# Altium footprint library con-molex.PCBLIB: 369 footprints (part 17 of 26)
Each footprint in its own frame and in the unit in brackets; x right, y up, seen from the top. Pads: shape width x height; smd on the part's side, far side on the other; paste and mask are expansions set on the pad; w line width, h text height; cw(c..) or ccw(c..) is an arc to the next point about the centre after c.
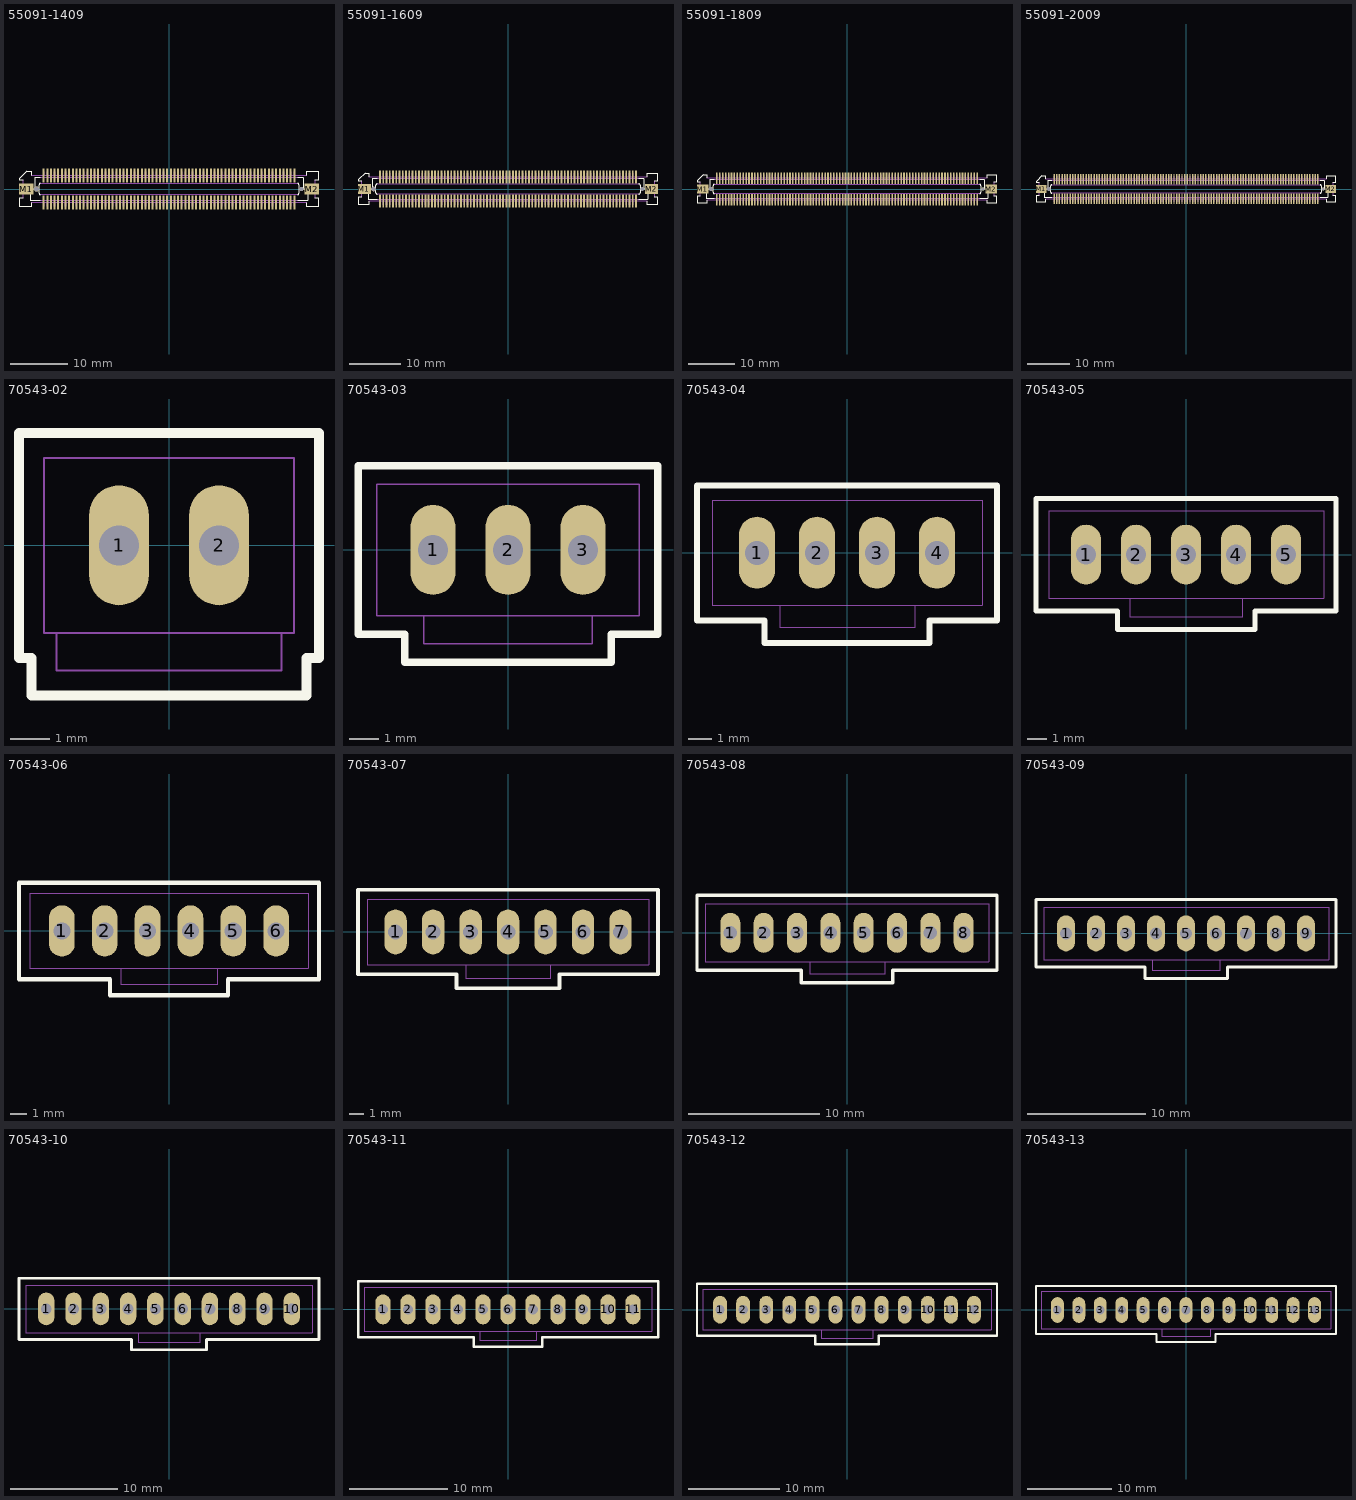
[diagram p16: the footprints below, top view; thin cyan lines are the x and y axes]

## 55091-1409 [mm]
pads (144):
  round 0.9 hole 0.9: 1(-23.16,0)
  rect 0.35x2.5 smd: 1(-21.907,2.35) 2(-21.907,-2.35) 3(-21.273,2.35) 4(-21.273,-2.35) 5(-20.637,2.35) 6(-20.637,-2.35) 7(-20.002,2.35) 8(-20.002,-2.35) 9(-19.367,2.35) 10(-19.367,-2.35) 11(-18.732,2.35) 12(-18.732,-2.35) 13(-18.098,2.35) 14(-18.098,-2.35) 15(-17.462,2.35) 16(-17.462,-2.35) 17(-16.828,2.35) 18(-16.828,-2.35) 19(-16.192,2.35) 20(-16.192,-2.35) 21(-15.557,2.35) 22(-15.557,-2.35) 23(-14.922,2.35) 24(-14.922,-2.35) 25(-14.287,2.35) 26(-14.287,-2.35) 27(-13.652,2.35) 28(-13.652,-2.35) 29(-13.018,2.35) 30(-13.018,-2.35) 31(-12.383,2.35) 32(-12.383,-2.35) 33(-11.747,2.35) 34(-11.747,-2.35) 35(-11.112,2.35) 36(-11.112,-2.35) 37(-10.477,2.35) 38(-10.477,-2.35) 39(-9.842,2.35) 40(-9.842,-2.35) 41(-9.207,2.35) 42(-9.207,-2.35) 43(-8.572,2.35) 44(-8.572,-2.35) 45(-7.938,2.35) 46(-7.938,-2.35) 47(-7.302,2.35) 48(-7.302,-2.35) 49(-6.667,2.35) 50(-6.667,-2.35) 51(-6.032,2.35) 52(-6.032,-2.35) 53(-5.397,2.35) 54(-5.397,-2.35) 55(-4.763,2.35) 56(-4.763,-2.35) 57(-4.127,2.35) 58(-4.127,-2.35) 59(-3.492,2.35) 60(-3.492,-2.35) 61(-2.857,2.35) 62(-2.857,-2.35) 63(-2.222,2.35) 64(-2.222,-2.35) 65(-1.587,2.35) 66(-1.587,-2.35) 67(-0.953,2.35) 68(-0.953,-2.35) 69(-0.318,2.35) 70(-0.318,-2.35) 71(0.318,2.35) 72(0.318,-2.35) 73(0.953,2.35) 74(0.953,-2.35) 75(1.587,2.35) 76(1.587,-2.35) 77(2.222,2.35) 78(2.222,-2.35) 79(2.857,2.35) 80(2.857,-2.35) 81(3.492,2.35) 82(3.492,-2.35) 83(4.127,2.35) 84(4.127,-2.35) 85(4.763,2.35) 86(4.763,-2.35) 87(5.397,2.35) 88(5.397,-2.35) 89(6.032,2.35) 90(6.032,-2.35) 91(6.667,2.35) 92(6.667,-2.35) 93(7.302,2.35) 94(7.302,-2.35) 95(7.938,2.35) 96(7.938,-2.35) 97(8.572,2.35) 98(8.572,-2.35) 99(9.207,2.35) 100(9.207,-2.35) 101(9.842,2.35) 102(9.842,-2.35) 103(10.477,2.35) 104(10.477,-2.35) 105(11.112,2.35) 106(11.112,-2.35) 107(11.747,2.35) 108(11.747,-2.35) 109(12.383,2.35) 110(12.383,-2.35) 111(13.018,2.35) 112(13.018,-2.35) 113(13.652,2.35) 114(13.652,-2.35) 115(14.287,2.35) 116(14.287,-2.35) 117(14.922,2.35) 118(14.922,-2.35) 119(15.557,2.35) 120(15.557,-2.35) 121(16.192,2.35) 122(16.192,-2.35) 123(16.828,2.35) 124(16.828,-2.35) 125(17.462,2.35) 126(17.462,-2.35) 127(18.098,2.35) 128(18.098,-2.35) 129(18.732,2.35) 130(18.732,-2.35) 131(19.367,2.35) 132(19.367,-2.35) 133(20.002,2.35) 134(20.002,-2.35) 135(20.637,2.35) 136(20.637,-2.35) 137(21.273,2.35) 138(21.273,-2.35) 139(21.907,2.35) 140(21.907,-2.35)
  round 0.7 hole 0.7: 1(23.16,0)
  rect 2.5x2 smd: M1(-24.975,0) M2(24.975,0)
Top Overlay:
  lines w0.203: -25.475,-1.5 -26.075,-1.5 -26.075,-3.1 -24.075,-3.1 -24.075,-2.4 ; -25.475,1.5 -26.075,1.5 -26.075,1.875 -24.85,3.1 -24.075,3.1 -24.075,2.4 ; -22.475,-2 -24.225,-2 -24.225,0 -23.475,0 -23.475,2 -22.475,2 ; -22.475,-1 cw(c-22.475,-0.75) -22.725,-0.75 -22.725,0.75 cw(c-22.475,0.75) -22.475,1 ; 22.475,-2 24.225,-2 24.225,0 23.475,0 23.475,2 22.475,2 ; 22.475,-1 ccw(c22.475,-0.75) 22.725,-0.75 22.725,0.75 ccw(c22.475,0.75) 22.475,1 ; 24.075,-2.4 24.075,-3.1 26.075,-3.1 26.075,-1.5 25.475,-1.5 ; 24.075,2.4 24.075,3.1 26.075,3.1 26.075,1.5 25.475,1.5
Top Solder:
  rectangle: -22.107,1.075 -21.708,3.625
  region: -21.708,-1.075 -22.107,-1.075 -22.107,-3.625 -21.708,-3.625
  rectangle: -21.472,1.075 -21.073,3.625
  region: -21.073,-1.075 -21.472,-1.075 -21.472,-3.625 -21.073,-3.625
  rectangle: -20.837,1.075 -20.438,3.625
  region: -20.438,-1.075 -20.837,-1.075 -20.837,-3.625 -20.438,-3.625
  rectangle: -20.202,1.075 -19.803,3.625
  region: -19.803,-1.075 -20.202,-1.075 -20.202,-3.625 -19.803,-3.625
  rectangle: -19.567,1.075 -19.168,3.625
  region: -19.168,-1.075 -19.567,-1.075 -19.567,-3.625 -19.168,-3.625
  rectangle: -18.932,1.075 -18.533,3.625
  region: -18.533,-1.075 -18.932,-1.075 -18.932,-3.625 -18.533,-3.625
  rectangle: -18.297,1.075 -17.898,3.625
  region: -17.898,-1.075 -18.297,-1.075 -18.297,-3.625 -17.898,-3.625
  rectangle: -17.662,1.075 -17.263,3.625
  region: -17.263,-1.075 -17.662,-1.075 -17.662,-3.625 -17.263,-3.625
  rectangle: -17.027,1.075 -16.628,3.625
  region: -16.628,-1.075 -17.027,-1.075 -17.027,-3.625 -16.628,-3.625
  rectangle: -16.392,1.075 -15.993,3.625
  region: -15.993,-1.075 -16.392,-1.075 -16.392,-3.625 -15.993,-3.625
  rectangle: -15.757,1.075 -15.358,3.625
  region: -15.358,-1.075 -15.757,-1.075 -15.757,-3.625 -15.358,-3.625
  rectangle: -15.122,1.075 -14.723,3.625
  region: -14.723,-1.075 -15.122,-1.075 -15.122,-3.625 -14.723,-3.625
  rectangle: -14.487,1.075 -14.088,3.625
  region: -14.088,-1.075 -14.487,-1.075 -14.487,-3.625 -14.088,-3.625
  rectangle: -13.852,1.075 -13.453,3.625
  region: -13.453,-1.075 -13.852,-1.075 -13.852,-3.625 -13.453,-3.625
  rectangle: -13.217,1.075 -12.818,3.625
  region: -12.818,-1.075 -13.217,-1.075 -13.217,-3.625 -12.818,-3.625
  rectangle: -12.582,1.075 -12.183,3.625
  region: -12.183,-1.075 -12.582,-1.075 -12.582,-3.625 -12.183,-3.625
  rectangle: -11.947,1.075 -11.548,3.625
  region: -11.548,-1.075 -11.947,-1.075 -11.947,-3.625 -11.548,-3.625
  rectangle: -11.312,1.075 -10.913,3.625
  region: -10.913,-1.075 -11.312,-1.075 -11.312,-3.625 -10.913,-3.625
  rectangle: -10.677,1.075 -10.278,3.625
  region: -10.278,-1.075 -10.677,-1.075 -10.677,-3.625 -10.278,-3.625
  rectangle: -10.042,1.075 -9.643,3.625
  region: -9.643,-1.075 -10.042,-1.075 -10.042,-3.625 -9.643,-3.625
  rectangle: -9.407,1.075 -9.008,3.625
  region: -9.008,-1.075 -9.407,-1.075 -9.407,-3.625 -9.008,-3.625
  rectangle: -8.772,1.075 -8.373,3.625
  region: -8.373,-1.075 -8.772,-1.075 -8.772,-3.625 -8.373,-3.625
  rectangle: -8.137,1.075 -7.738,3.625
  region: -7.738,-1.075 -8.137,-1.075 -8.137,-3.625 -7.738,-3.625
  rectangle: -7.502,1.075 -7.103,3.625
  region: -7.103,-1.075 -7.502,-1.075 -7.502,-3.625 -7.103,-3.625
  rectangle: -6.867,1.075 -6.468,3.625
  region: -6.468,-1.075 -6.867,-1.075 -6.867,-3.625 -6.468,-3.625
  rectangle: -6.232,1.075 -5.833,3.625
  region: -5.833,-1.075 -6.232,-1.075 -6.232,-3.625 -5.833,-3.625
  rectangle: -5.597,1.075 -5.198,3.625
  region: -5.198,-1.075 -5.597,-1.075 -5.597,-3.625 -5.198,-3.625
  rectangle: -4.962,1.075 -4.563,3.625
  region: -4.563,-1.075 -4.962,-1.075 -4.962,-3.625 -4.563,-3.625
  rectangle: -4.327,1.075 -3.928,3.625
  region: -3.928,-1.075 -4.327,-1.075 -4.327,-3.625 -3.928,-3.625
  rectangle: -3.692,1.075 -3.293,3.625
  region: -3.293,-1.075 -3.692,-1.075 -3.692,-3.625 -3.293,-3.625
  rectangle: -3.057,1.075 -2.658,3.625
  region: -2.658,-1.075 -3.057,-1.075 -3.057,-3.625 -2.658,-3.625
  rectangle: -2.422,1.075 -2.023,3.625
  region: -2.023,-1.075 -2.422,-1.075 -2.422,-3.625 -2.023,-3.625
  rectangle: -1.787,1.075 -1.388,3.625
  region: -1.388,-1.075 -1.787,-1.075 -1.787,-3.625 -1.388,-3.625
  rectangle: -1.152,1.075 -0.753,3.625
  region: -0.753,-1.075 -1.152,-1.075 -1.152,-3.625 -0.753,-3.625
  rectangle: -0.517,1.075 -0.118,3.625
  region: -0.118,-1.075 -0.517,-1.075 -0.517,-3.625 -0.118,-3.625
  rectangle: 0.118,1.075 0.517,3.625
  region: 0.517,-1.075 0.118,-1.075 0.118,-3.625 0.517,-3.625
  rectangle: 0.753,1.075 1.152,3.625
  region: 1.152,-1.075 0.753,-1.075 0.753,-3.625 1.152,-3.625
  rectangle: 1.388,1.075 1.787,3.625
  region: 1.787,-1.075 1.388,-1.075 1.388,-3.625 1.787,-3.625
  rectangle: 2.023,1.075 2.422,3.625
  region: 2.422,-1.075 2.023,-1.075 2.023,-3.625 2.422,-3.625
  rectangle: 2.658,1.075 3.057,3.625
  region: 3.057,-1.075 2.658,-1.075 2.658,-3.625 3.057,-3.625
  rectangle: 3.293,1.075 3.692,3.625
  region: 3.692,-1.075 3.293,-1.075 3.293,-3.625 3.692,-3.625
  rectangle: 3.928,1.075 4.327,3.625
  region: 4.327,-1.075 3.928,-1.075 3.928,-3.625 4.327,-3.625
  rectangle: 4.563,1.075 4.962,3.625
  region: 4.962,-1.075 4.563,-1.075 4.563,-3.625 4.962,-3.625
  rectangle: 5.198,1.075 5.597,3.625
  region: 5.597,-1.075 5.198,-1.075 5.198,-3.625 5.597,-3.625
  rectangle: 5.833,1.075 6.232,3.625
  region: 6.232,-1.075 5.833,-1.075 5.833,-3.625 6.232,-3.625
  rectangle: 6.468,1.075 6.867,3.625
  region: 6.867,-1.075 6.468,-1.075 6.468,-3.625 6.867,-3.625
  rectangle: 7.103,1.075 7.502,3.625
  region: 7.502,-1.075 7.103,-1.075 7.103,-3.625 7.502,-3.625
  rectangle: 7.738,1.075 8.137,3.625
  region: 8.137,-1.075 7.738,-1.075 7.738,-3.625 8.137,-3.625
  rectangle: 8.373,1.075 8.772,3.625
  region: 8.772,-1.075 8.373,-1.075 8.373,-3.625 8.772,-3.625
  rectangle: 9.008,1.075 9.407,3.625
  region: 9.407,-1.075 9.008,-1.075 9.008,-3.625 9.407,-3.625
  rectangle: 9.643,1.075 10.042,3.625
  region: 10.042,-1.075 9.643,-1.075 9.643,-3.625 10.042,-3.625
  rectangle: 10.278,1.075 10.677,3.625
  region: 10.677,-1.075 10.278,-1.075 10.278,-3.625 10.677,-3.625
  rectangle: 10.913,1.075 11.312,3.625
  region: 11.312,-1.075 10.913,-1.075 10.913,-3.625 11.312,-3.625
  rectangle: 11.548,1.075 11.947,3.625
  region: 11.947,-1.075 11.548,-1.075 11.548,-3.625 11.947,-3.625
  rectangle: 12.183,1.075 12.582,3.625
  region: 12.582,-1.075 12.183,-1.075 12.183,-3.625 12.582,-3.625
  rectangle: 12.818,1.075 13.217,3.625
  region: 13.217,-1.075 12.818,-1.075 12.818,-3.625 13.217,-3.625
  rectangle: 13.453,1.075 13.852,3.625
  region: 13.852,-1.075 13.453,-1.075 13.453,-3.625 13.852,-3.625
  rectangle: 14.088,1.075 14.487,3.625
  region: 14.487,-1.075 14.088,-1.075 14.088,-3.625 14.487,-3.625
  rectangle: 14.723,1.075 15.122,3.625
  region: 15.122,-1.075 14.723,-1.075 14.723,-3.625 15.122,-3.625
  rectangle: 15.358,1.075 15.757,3.625
  region: 15.757,-1.075 15.358,-1.075 15.358,-3.625 15.757,-3.625
  rectangle: 15.993,1.075 16.392,3.625
  region: 16.392,-1.075 15.993,-1.075 15.993,-3.625 16.392,-3.625
  rectangle: 16.628,1.075 17.027,3.625
  region: 17.027,-1.075 16.628,-1.075 16.628,-3.625 17.027,-3.625
  rectangle: 17.263,1.075 17.662,3.625
  region: 17.662,-1.075 17.263,-1.075 17.263,-3.625 17.662,-3.625
  rectangle: 17.898,1.075 18.297,3.625
  region: 18.297,-1.075 17.898,-1.075 17.898,-3.625 18.297,-3.625
  rectangle: 18.533,1.075 18.932,3.625
  region: 18.932,-1.075 18.533,-1.075 18.533,-3.625 18.932,-3.625
  rectangle: 19.168,1.075 19.567,3.625
  region: 19.567,-1.075 19.168,-1.075 19.168,-3.625 19.567,-3.625
  rectangle: 19.803,1.075 20.202,3.625
  region: 20.202,-1.075 19.803,-1.075 19.803,-3.625 20.202,-3.625
  rectangle: 20.438,1.075 20.837,3.625
  region: 20.837,-1.075 20.438,-1.075 20.438,-3.625 20.837,-3.625
  rectangle: 21.073,1.075 21.472,3.625
  region: 21.472,-1.075 21.073,-1.075 21.073,-3.625 21.472,-3.625
  rectangle: 21.708,1.075 22.107,3.625
  region: 22.107,-1.075 21.708,-1.075 21.708,-3.625 22.107,-3.625
Mechanical 16:
  rectangle: -22.058,-3.1 -21.757,-2.375
  region: -21.757,3.1 -22.058,3.1 -22.058,2.375 -21.757,2.375
  rectangle: -21.423,-3.1 -21.122,-2.375
  region: -21.122,3.1 -21.423,3.1 -21.423,2.375 -21.122,2.375
  rectangle: -20.788,-3.1 -20.487,-2.375
  region: -20.487,3.1 -20.788,3.1 -20.788,2.375 -20.487,2.375
  rectangle: -20.153,-3.1 -19.852,-2.375
  region: -19.852,3.1 -20.153,3.1 -20.153,2.375 -19.852,2.375
  rectangle: -19.518,-3.1 -19.217,-2.375
  region: -19.217,3.1 -19.518,3.1 -19.518,2.375 -19.217,2.375
  rectangle: -18.883,-3.1 -18.582,-2.375
  region: -18.582,3.1 -18.883,3.1 -18.883,2.375 -18.582,2.375
  rectangle: -18.248,-3.1 -17.947,-2.375
  region: -17.947,3.1 -18.248,3.1 -18.248,2.375 -17.947,2.375
  rectangle: -17.613,-3.1 -17.312,-2.375
  region: -17.312,3.1 -17.613,3.1 -17.613,2.375 -17.312,2.375
  rectangle: -16.978,-3.1 -16.677,-2.375
  region: -16.677,3.1 -16.978,3.1 -16.978,2.375 -16.677,2.375
  rectangle: -16.343,-3.1 -16.042,-2.375
  region: -16.042,3.1 -16.343,3.1 -16.343,2.375 -16.042,2.375
  rectangle: -15.708,-3.1 -15.407,-2.375
  region: -15.407,3.1 -15.708,3.1 -15.708,2.375 -15.407,2.375
  rectangle: -15.073,-3.1 -14.772,-2.375
  region: -14.772,3.1 -15.073,3.1 -15.073,2.375 -14.772,2.375
  rectangle: -14.438,-3.1 -14.137,-2.375
  region: -14.137,3.1 -14.438,3.1 -14.438,2.375 -14.137,2.375
  rectangle: -13.803,-3.1 -13.502,-2.375
  region: -13.502,3.1 -13.803,3.1 -13.803,2.375 -13.502,2.375
  rectangle: -13.168,-3.1 -12.867,-2.375
  region: -12.867,3.1 -13.168,3.1 -13.168,2.375 -12.867,2.375
  rectangle: -12.533,-3.1 -12.232,-2.375
  region: -12.232,3.1 -12.533,3.1 -12.533,2.375 -12.232,2.375
  rectangle: -11.898,-3.1 -11.597,-2.375
  region: -11.597,3.1 -11.898,3.1 -11.898,2.375 -11.597,2.375
  rectangle: -11.263,-3.1 -10.962,-2.375
  region: -10.962,3.1 -11.263,3.1 -11.263,2.375 -10.962,2.375
  rectangle: -10.628,-3.1 -10.327,-2.375
  region: -10.327,3.1 -10.628,3.1 -10.628,2.375 -10.327,2.375
  rectangle: -9.993,-3.1 -9.692,-2.375
  region: -9.692,3.1 -9.993,3.1 -9.993,2.375 -9.692,2.375
  rectangle: -9.358,-3.1 -9.057,-2.375
  region: -9.057,3.1 -9.358,3.1 -9.358,2.375 -9.057,2.375
  rectangle: -8.723,-3.1 -8.422,-2.375
  region: -8.422,3.1 -8.723,3.1 -8.723,2.375 -8.422,2.375
  rectangle: -8.088,-3.1 -7.787,-2.375
  region: -7.787,3.1 -8.088,3.1 -8.088,2.375 -7.787,2.375
  rectangle: -7.453,-3.1 -7.152,-2.375
  region: -7.152,3.1 -7.453,3.1 -7.453,2.375 -7.152,2.375
  rectangle: -6.818,-3.1 -6.517,-2.375
  region: -6.517,3.1 -6.818,3.1 -6.818,2.375 -6.517,2.375
  rectangle: -6.183,-3.1 -5.882,-2.375
  region: -5.882,3.1 -6.183,3.1 -6.183,2.375 -5.882,2.375
  rectangle: -5.548,-3.1 -5.247,-2.375
  region: -5.247,3.1 -5.548,3.1 -5.548,2.375 -5.247,2.375
  rectangle: -4.913,-3.1 -4.612,-2.375
  region: -4.612,3.1 -4.913,3.1 -4.913,2.375 -4.612,2.375
  rectangle: -4.278,-3.1 -3.977,-2.375
  region: -3.977,3.1 -4.278,3.1 -4.278,2.375 -3.977,2.375
  rectangle: -3.643,-3.1 -3.342,-2.375
  region: -3.342,3.1 -3.643,3.1 -3.643,2.375 -3.342,2.375
  rectangle: -3.008,-3.1 -2.707,-2.375
  region: -2.707,3.1 -3.008,3.1 -3.008,2.375 -2.707,2.375
  rectangle: -2.373,-3.1 -2.072,-2.375
  region: -2.072,3.1 -2.373,3.1 -2.373,2.375 -2.072,2.375
  rectangle: -1.738,-3.1 -1.437,-2.375
  region: -1.437,3.1 -1.738,3.1 -1.738,2.375 -1.437,2.375
  rectangle: -1.103,-3.1 -0.802,-2.375
  region: -0.802,3.1 -1.103,3.1 -1.103,2.375 -0.802,2.375
  rectangle: -0.468,-3.1 -0.167,-2.375
  region: -0.167,3.1 -0.468,3.1 -0.468,2.375 -0.167,2.375
  rectangle: 0.167,-3.1 0.468,-2.375
  region: 0.468,3.1 0.167,3.1 0.167,2.375 0.468,2.375
  rectangle: 0.802,-3.1 1.103,-2.375
  region: 1.103,3.1 0.802,3.1 0.802,2.375 1.103,2.375
  rectangle: 1.437,-3.1 1.738,-2.375
  region: 1.738,3.1 1.437,3.1 1.437,2.375 1.738,2.375
  rectangle: 2.072,-3.1 2.373,-2.375
  region: 2.373,3.1 2.072,3.1 2.072,2.375 2.373,2.375
  rectangle: 2.707,-3.1 3.008,-2.375
  region: 3.008,3.1 2.707,3.1 2.707,2.375 3.008,2.375
  rectangle: 3.342,-3.1 3.643,-2.375
  region: 3.643,3.1 3.342,3.1 3.342,2.375 3.643,2.375
  rectangle: 3.977,-3.1 4.278,-2.375
  region: 4.278,3.1 3.977,3.1 3.977,2.375 4.278,2.375
  rectangle: 4.612,-3.1 4.913,-2.375
  region: 4.913,3.1 4.612,3.1 4.612,2.375 4.913,2.375
  rectangle: 5.247,-3.1 5.548,-2.375
  region: 5.548,3.1 5.247,3.1 5.247,2.375 5.548,2.375
  rectangle: 5.882,-3.1 6.183,-2.375
  region: 6.183,3.1 5.882,3.1 5.882,2.375 6.183,2.375
  rectangle: 6.517,-3.1 6.818,-2.375
  region: 6.818,3.1 6.517,3.1 6.517,2.375 6.818,2.375
  rectangle: 7.152,-3.1 7.453,-2.375
  region: 7.453,3.1 7.152,3.1 7.152,2.375 7.453,2.375
  rectangle: 7.787,-3.1 8.088,-2.375
  region: 8.088,3.1 7.787,3.1 7.787,2.375 8.088,2.375
  rectangle: 8.422,-3.1 8.723,-2.375
  region: 8.723,3.1 8.422,3.1 8.422,2.375 8.723,2.375
  rectangle: 9.057,-3.1 9.358,-2.375
  region: 9.358,3.1 9.057,3.1 9.057,2.375 9.358,2.375
  rectangle: 9.692,-3.1 9.993,-2.375
  region: 9.993,3.1 9.692,3.1 9.692,2.375 9.993,2.375
  rectangle: 10.327,-3.1 10.628,-2.375
  region: 10.628,3.1 10.327,3.1 10.327,2.375 10.628,2.375
  rectangle: 10.962,-3.1 11.263,-2.375
  region: 11.263,3.1 10.962,3.1 10.962,2.375 11.263,2.375
  rectangle: 11.597,-3.1 11.898,-2.375
  region: 11.898,3.1 11.597,3.1 11.597,2.375 11.898,2.375
  rectangle: 12.232,-3.1 12.533,-2.375
  region: 12.533,3.1 12.232,3.1 12.232,2.375 12.533,2.375
  rectangle: 12.867,-3.1 13.168,-2.375
  region: 13.168,3.1 12.867,3.1 12.867,2.375 13.168,2.375
  rectangle: 13.502,-3.1 13.803,-2.375
  region: 13.803,3.1 13.502,3.1 13.502,2.375 13.803,2.375
  rectangle: 14.137,-3.1 14.438,-2.375
  region: 14.438,3.1 14.137,3.1 14.137,2.375 14.438,2.375
  rectangle: 14.772,-3.1 15.073,-2.375
  region: 15.073,3.1 14.772,3.1 14.772,2.375 15.073,2.375
  rectangle: 15.407,-3.1 15.708,-2.375
  region: 15.708,3.1 15.407,3.1 15.407,2.375 15.708,2.375
  rectangle: 16.042,-3.1 16.343,-2.375
  region: 16.343,3.1 16.042,3.1 16.042,2.375 16.343,2.375
  rectangle: 16.677,-3.1 16.978,-2.375
  region: 16.978,3.1 16.677,3.1 16.677,2.375 16.978,2.375
  rectangle: 17.312,-3.1 17.613,-2.375
  region: 17.613,3.1 17.312,3.1 17.312,2.375 17.613,2.375
  rectangle: 17.947,-3.1 18.248,-2.375
  region: 18.248,3.1 17.947,3.1 17.947,2.375 18.248,2.375
  rectangle: 18.582,-3.1 18.883,-2.375
  region: 18.883,3.1 18.582,3.1 18.582,2.375 18.883,2.375
  rectangle: 19.217,-3.1 19.518,-2.375
  region: 19.518,3.1 19.217,3.1 19.217,2.375 19.518,2.375
  rectangle: 19.852,-3.1 20.153,-2.375
  region: 20.153,3.1 19.852,3.1 19.852,2.375 20.153,2.375
  rectangle: 20.487,-3.1 20.788,-2.375
  region: 20.788,3.1 20.487,3.1 20.487,2.375 20.788,2.375
  rectangle: 21.122,-3.1 21.423,-2.375
  region: 21.423,3.1 21.122,3.1 21.122,2.375 21.423,2.375
  rectangle: 21.757,-3.1 22.058,-2.375
  region: 22.058,3.1 21.757,3.1 21.757,2.375 22.058,2.375
  lines w0.203: -25.475,-1.5 -25.475,1.5 ; -24.075,-2.4 24.075,-2.4 ; -24.075,2.4 24.075,2.4 ; -22.475,-2 22.475,-2 ; -22.475,-1 22.475,-1 ; -22.475,1 22.475,1 ; -22.475,2 22.475,2 ; 25.475,-1.5 25.475,1.5

## 55091-1609 [mm]
pads (164):
  round 0.9 hole 0.9: 1(-26.335,0)
  rect 0.35x2.5 smd: 1(-25.082,2.35) 2(-25.082,-2.35) 3(-24.447,2.35) 4(-24.447,-2.35) 5(-23.812,2.35) 6(-23.812,-2.35) 7(-23.177,2.35) 8(-23.177,-2.35) 9(-22.543,2.35) 10(-22.543,-2.35) 11(-21.907,2.35) 12(-21.907,-2.35) 13(-21.273,2.35) 14(-21.273,-2.35) 15(-20.637,2.35) 16(-20.637,-2.35) 17(-20.002,2.35) 18(-20.002,-2.35) 19(-19.367,2.35) 20(-19.367,-2.35) 21(-18.732,2.35) 22(-18.732,-2.35) 23(-18.098,2.35) 24(-18.098,-2.35) 25(-17.462,2.35) 26(-17.462,-2.35) 27(-16.828,2.35) 28(-16.828,-2.35) 29(-16.192,2.35) 30(-16.192,-2.35) 31(-15.557,2.35) 32(-15.557,-2.35) 33(-14.922,2.35) 34(-14.922,-2.35) 35(-14.287,2.35) 36(-14.287,-2.35) 37(-13.652,2.35) 38(-13.652,-2.35) 39(-13.018,2.35) 40(-13.018,-2.35) 41(-12.383,2.35) 42(-12.383,-2.35) 43(-11.747,2.35) 44(-11.747,-2.35) 45(-11.112,2.35) 46(-11.112,-2.35) 47(-10.477,2.35) 48(-10.477,-2.35) 49(-9.842,2.35) 50(-9.842,-2.35) 51(-9.207,2.35) 52(-9.207,-2.35) 53(-8.572,2.35) 54(-8.572,-2.35) 55(-7.938,2.35) 56(-7.938,-2.35) 57(-7.302,2.35) 58(-7.302,-2.35) 59(-6.667,2.35) 60(-6.667,-2.35) 61(-6.032,2.35) 62(-6.032,-2.35) 63(-5.397,2.35) 64(-5.397,-2.35) 65(-4.763,2.35) 66(-4.763,-2.35) 67(-4.127,2.35) 68(-4.127,-2.35) 69(-3.492,2.35) 70(-3.492,-2.35) 71(-2.857,2.35) 72(-2.857,-2.35) 73(-2.222,2.35) 74(-2.222,-2.35) 75(-1.587,2.35) 76(-1.587,-2.35) 77(-0.953,2.35) 78(-0.953,-2.35) 79(-0.318,2.35) 80(-0.318,-2.35) 81(0.318,2.35) 82(0.318,-2.35) 83(0.953,2.35) 84(0.953,-2.35) 85(1.587,2.35) 86(1.587,-2.35) 87(2.222,2.35) 88(2.222,-2.35) 89(2.857,2.35) 90(2.857,-2.35) 91(3.492,2.35) 92(3.492,-2.35) 93(4.127,2.35) 94(4.127,-2.35) 95(4.763,2.35) 96(4.763,-2.35) 97(5.397,2.35) 98(5.397,-2.35) 99(6.032,2.35) 100(6.032,-2.35) 101(6.667,2.35) 102(6.667,-2.35) 103(7.302,2.35) 104(7.302,-2.35) 105(7.938,2.35) 106(7.938,-2.35) 107(8.572,2.35) 108(8.572,-2.35) 109(9.207,2.35) 110(9.207,-2.35) 111(9.842,2.35) 112(9.842,-2.35) 113(10.477,2.35) 114(10.477,-2.35) 115(11.112,2.35) 116(11.112,-2.35) 117(11.747,2.35) 118(11.747,-2.35) 119(12.383,2.35) 120(12.383,-2.35) 121(13.018,2.35) 122(13.018,-2.35) 123(13.652,2.35) 124(13.652,-2.35) 125(14.287,2.35) 126(14.287,-2.35) 127(14.922,2.35) 128(14.922,-2.35) 129(15.557,2.35) 130(15.557,-2.35) 131(16.192,2.35) 132(16.192,-2.35) 133(16.828,2.35) 134(16.828,-2.35) 135(17.462,2.35) 136(17.462,-2.35) 137(18.098,2.35) 138(18.098,-2.35) 139(18.732,2.35) 140(18.732,-2.35) 141(19.367,2.35) 142(19.367,-2.35) 143(20.002,2.35) 144(20.002,-2.35) 145(20.637,2.35) 146(20.637,-2.35) 147(21.273,2.35) 148(21.273,-2.35) 149(21.907,2.35) 150(21.907,-2.35) 151(22.543,2.35) 152(22.543,-2.35) 153(23.177,2.35) 154(23.177,-2.35) 155(23.812,2.35) 156(23.812,-2.35) 157(24.447,2.35) 158(24.447,-2.35) 159(25.082,2.35) 160(25.082,-2.35)
  round 0.7 hole 0.7: 1(26.335,0)
  rect 2.5x2 smd: M1(-28.15,0) M2(28.15,0)
Top Overlay:
  lines w0.203: -28.65,-1.5 -29.25,-1.5 -29.25,-3.1 -27.25,-3.1 -27.25,-2.4 ; -28.65,1.5 -29.25,1.5 -29.25,1.875 -28.025,3.1 -27.25,3.1 -27.25,2.4 ; -25.65,-2 -27.4,-2 -27.4,0 -26.65,0 -26.65,2 -25.65,2 ; -25.65,-1 cw(c-25.65,-0.75) -25.9,-0.75 -25.9,0.75 cw(c-25.65,0.75) -25.65,1 ; 25.65,-2 27.4,-2 27.4,0 26.65,0 26.65,2 25.65,2 ; 25.65,-1 ccw(c25.65,-0.75) 25.9,-0.75 25.9,0.75 ccw(c25.65,0.75) 25.65,1 ; 27.25,-2.4 27.25,-3.1 29.25,-3.1 29.25,-1.5 28.65,-1.5 ; 27.25,2.4 27.25,3.1 29.25,3.1 29.25,1.5 28.65,1.5
Top Solder:
  drawing of 160 lines, arcs and shapes, not listed
Mechanical 16:
  drawing of 168 lines, arcs and shapes, not listed

## 55091-1809 [mm]
pads (184):
  round 0.9 hole 0.9: 1(-29.51,0)
  rect 0.35x2.5 smd: 1(-28.258,2.35) 2(-28.258,-2.35) 3(-27.622,2.35) 4(-27.622,-2.35) 5(-26.987,2.35) 6(-26.987,-2.35) 7(-26.352,2.35) 8(-26.352,-2.35) 9(-25.717,2.35) 10(-25.717,-2.35) 11(-25.082,2.35) 12(-25.082,-2.35) 13(-24.447,2.35) 14(-24.447,-2.35) 15(-23.812,2.35) 16(-23.812,-2.35) 17(-23.177,2.35) 18(-23.177,-2.35) 19(-22.543,2.35) 20(-22.543,-2.35) 21(-21.907,2.35) 22(-21.907,-2.35) 23(-21.273,2.35) 24(-21.273,-2.35) 25(-20.637,2.35) 26(-20.637,-2.35) 27(-20.002,2.35) 28(-20.002,-2.35) 29(-19.367,2.35) 30(-19.367,-2.35) 31(-18.732,2.35) 32(-18.732,-2.35) 33(-18.098,2.35) 34(-18.098,-2.35) 35(-17.462,2.35) 36(-17.462,-2.35) 37(-16.828,2.35) 38(-16.828,-2.35) 39(-16.192,2.35) 40(-16.192,-2.35) 41(-15.557,2.35) 42(-15.557,-2.35) 43(-14.922,2.35) 44(-14.922,-2.35) 45(-14.287,2.35) 46(-14.287,-2.35) 47(-13.652,2.35) 48(-13.652,-2.35) 49(-13.018,2.35) 50(-13.018,-2.35) 51(-12.383,2.35) 52(-12.383,-2.35) 53(-11.747,2.35) 54(-11.747,-2.35) 55(-11.112,2.35) 56(-11.112,-2.35) 57(-10.477,2.35) 58(-10.477,-2.35) 59(-9.842,2.35) 60(-9.842,-2.35) 61(-9.207,2.35) 62(-9.207,-2.35) 63(-8.572,2.35) 64(-8.572,-2.35) 65(-7.938,2.35) 66(-7.938,-2.35) 67(-7.302,2.35) 68(-7.302,-2.35) 69(-6.667,2.35) 70(-6.667,-2.35) 71(-6.032,2.35) 72(-6.032,-2.35) 73(-5.397,2.35) 74(-5.397,-2.35) 75(-4.763,2.35) 76(-4.763,-2.35) 77(-4.127,2.35) 78(-4.127,-2.35) 79(-3.492,2.35) 80(-3.492,-2.35) 81(-2.857,2.35) 82(-2.857,-2.35) 83(-2.222,2.35) 84(-2.222,-2.35) 85(-1.587,2.35) 86(-1.587,-2.35) 87(-0.953,2.35) 88(-0.953,-2.35) 89(-0.318,2.35) 90(-0.318,-2.35) 91(0.318,2.35) 92(0.318,-2.35) 93(0.953,2.35) 94(0.953,-2.35) 95(1.587,2.35) 96(1.587,-2.35) 97(2.222,2.35) 98(2.222,-2.35) 99(2.857,2.35) 100(2.857,-2.35) 101(3.492,2.35) 102(3.492,-2.35) 103(4.127,2.35) 104(4.127,-2.35) 105(4.763,2.35) 106(4.763,-2.35) 107(5.397,2.35) 108(5.397,-2.35) 109(6.032,2.35) 110(6.032,-2.35) 111(6.667,2.35) 112(6.667,-2.35) 113(7.302,2.35) 114(7.302,-2.35) 115(7.938,2.35) 116(7.938,-2.35) 117(8.572,2.35) 118(8.572,-2.35) 119(9.207,2.35) 120(9.207,-2.35) 121(9.842,2.35) 122(9.842,-2.35) 123(10.477,2.35) 124(10.477,-2.35) 125(11.112,2.35) 126(11.112,-2.35) 127(11.747,2.35) 128(11.747,-2.35) 129(12.383,2.35) 130(12.383,-2.35) 131(13.018,2.35) 132(13.018,-2.35) 133(13.652,2.35) 134(13.652,-2.35) 135(14.287,2.35) 136(14.287,-2.35) 137(14.922,2.35) 138(14.922,-2.35) 139(15.557,2.35) 140(15.557,-2.35) 141(16.192,2.35) 142(16.192,-2.35) 143(16.828,2.35) 144(16.828,-2.35) 145(17.462,2.35) 146(17.462,-2.35) 147(18.098,2.35) 148(18.098,-2.35) 149(18.732,2.35) 150(18.732,-2.35) 151(19.367,2.35) 152(19.367,-2.35) 153(20.002,2.35) 154(20.002,-2.35) 155(20.637,2.35) 156(20.637,-2.35) 157(21.273,2.35) 158(21.273,-2.35) 159(21.907,2.35) 160(21.907,-2.35) 161(22.543,2.35) 162(22.543,-2.35) 163(23.177,2.35) 164(23.177,-2.35) 165(23.812,2.35) 166(23.812,-2.35) 167(24.447,2.35) 168(24.447,-2.35) 169(25.082,2.35) 170(25.082,-2.35) 171(25.717,2.35) 172(25.717,-2.35) 173(26.352,2.35) 174(26.352,-2.35) 175(26.987,2.35) 176(26.987,-2.35) 177(27.622,2.35) 178(27.622,-2.35) 179(28.258,2.35) 180(28.258,-2.35)
  round 0.7 hole 0.7: 1(29.51,0)
  rect 2.5x2 smd: M1(-31.325,0) M2(31.325,0)
Top Overlay:
  lines w0.203: -31.825,-1.5 -32.425,-1.5 -32.425,-3.1 -30.425,-3.1 -30.425,-2.4 ; -31.825,1.5 -32.425,1.5 -32.425,1.875 -31.2,3.1 -30.425,3.1 -30.425,2.4 ; -28.825,-2 -30.575,-2 -30.575,0 -29.825,0 -29.825,2 -28.825,2 ; -28.825,-1 cw(c-28.825,-0.75) -29.075,-0.75 -29.075,0.75 cw(c-28.825,0.75) -28.825,1 ; 28.825,-2 30.575,-2 30.575,0 29.825,0 29.825,2 28.825,2 ; 28.825,-1 ccw(c28.825,-0.75) 29.075,-0.75 29.075,0.75 ccw(c28.825,0.75) 28.825,1 ; 30.425,-2.4 30.425,-3.1 32.425,-3.1 32.425,-1.5 31.825,-1.5 ; 30.425,2.4 30.425,3.1 32.425,3.1 32.425,1.5 31.825,1.5
Top Solder:
  drawing of 180 lines, arcs and shapes, not listed
Mechanical 16:
  drawing of 188 lines, arcs and shapes, not listed

## 55091-2009 [mm]
pads (204):
  round 0.9 hole 0.9: 1(-32.685,0)
  rect 0.35x2.5 smd: 1(-31.432,2.35) 2(-31.432,-2.35) 3(-30.797,2.35) 4(-30.797,-2.35) 5(-30.162,2.35) 6(-30.162,-2.35) 7(-29.527,2.35) 8(-29.527,-2.35) 9(-28.892,2.35) 10(-28.892,-2.35) 11(-28.258,2.35) 12(-28.258,-2.35) 13(-27.622,2.35) 14(-27.622,-2.35) 15(-26.987,2.35) 16(-26.987,-2.35) 17(-26.352,2.35) 18(-26.352,-2.35) 19(-25.717,2.35) 20(-25.717,-2.35) 21(-25.082,2.35) 22(-25.082,-2.35) 23(-24.447,2.35) 24(-24.447,-2.35) 25(-23.812,2.35) 26(-23.812,-2.35) 27(-23.177,2.35) 28(-23.177,-2.35) 29(-22.543,2.35) 30(-22.543,-2.35) 31(-21.907,2.35) 32(-21.907,-2.35) 33(-21.273,2.35) 34(-21.273,-2.35) 35(-20.637,2.35) 36(-20.637,-2.35) 37(-20.002,2.35) 38(-20.002,-2.35) 39(-19.367,2.35) 40(-19.367,-2.35) 41(-18.732,2.35) 42(-18.732,-2.35) 43(-18.098,2.35) 44(-18.098,-2.35) 45(-17.462,2.35) 46(-17.462,-2.35) 47(-16.828,2.35) 48(-16.828,-2.35) 49(-16.192,2.35) 50(-16.192,-2.35) 51(-15.557,2.35) 52(-15.557,-2.35) 53(-14.922,2.35) 54(-14.922,-2.35) 55(-14.287,2.35) 56(-14.287,-2.35) 57(-13.652,2.35) 58(-13.652,-2.35) 59(-13.018,2.35) 60(-13.018,-2.35) 61(-12.383,2.35) 62(-12.383,-2.35) 63(-11.747,2.35) 64(-11.747,-2.35) 65(-11.112,2.35) 66(-11.112,-2.35) 67(-10.477,2.35) 68(-10.477,-2.35) 69(-9.842,2.35) 70(-9.842,-2.35) 71(-9.207,2.35) 72(-9.207,-2.35) 73(-8.572,2.35) 74(-8.572,-2.35) 75(-7.938,2.35) 76(-7.938,-2.35) 77(-7.302,2.35) 78(-7.302,-2.35) 79(-6.667,2.35) 80(-6.667,-2.35) 81(-6.032,2.35) 82(-6.032,-2.35) 83(-5.397,2.35) 84(-5.397,-2.35) 85(-4.763,2.35) 86(-4.763,-2.35) 87(-4.127,2.35) 88(-4.127,-2.35) 89(-3.492,2.35) 90(-3.492,-2.35) 91(-2.857,2.35) 92(-2.857,-2.35) 93(-2.222,2.35) 94(-2.222,-2.35) 95(-1.587,2.35) 96(-1.587,-2.35) 97(-0.953,2.35) 98(-0.953,-2.35) 99(-0.318,2.35) 100(-0.318,-2.35) 101(0.318,2.35) 102(0.318,-2.35) 103(0.953,2.35) 104(0.953,-2.35) 105(1.587,2.35) 106(1.587,-2.35) 107(2.222,2.35) 108(2.222,-2.35) 109(2.857,2.35) 110(2.857,-2.35) 111(3.492,2.35) 112(3.492,-2.35) 113(4.127,2.35) 114(4.127,-2.35) 115(4.763,2.35) 116(4.763,-2.35) 117(5.397,2.35) 118(5.397,-2.35) 119(6.032,2.35) 120(6.032,-2.35) 121(6.667,2.35) 122(6.667,-2.35) 123(7.302,2.35) 124(7.302,-2.35) 125(7.938,2.35) 126(7.938,-2.35) 127(8.572,2.35) 128(8.572,-2.35) 129(9.207,2.35) 130(9.207,-2.35) 131(9.842,2.35) 132(9.842,-2.35) 133(10.477,2.35) 134(10.477,-2.35) 135(11.112,2.35) 136(11.112,-2.35) 137(11.747,2.35) 138(11.747,-2.35) 139(12.383,2.35) 140(12.383,-2.35) 141(13.018,2.35) 142(13.018,-2.35) 143(13.652,2.35) 144(13.652,-2.35) 145(14.287,2.35) 146(14.287,-2.35) 147(14.922,2.35) 148(14.922,-2.35) 149(15.557,2.35) 150(15.557,-2.35) 151(16.192,2.35) 152(16.192,-2.35) 153(16.828,2.35) 154(16.828,-2.35) 155(17.462,2.35) 156(17.462,-2.35) 157(18.098,2.35) 158(18.098,-2.35) 159(18.732,2.35) 160(18.732,-2.35) 161(19.367,2.35) 162(19.367,-2.35) 163(20.002,2.35) 164(20.002,-2.35) 165(20.637,2.35) 166(20.637,-2.35) 167(21.273,2.35) 168(21.273,-2.35) 169(21.907,2.35) 170(21.907,-2.35) 171(22.543,2.35) 172(22.543,-2.35) 173(23.177,2.35) 174(23.177,-2.35) 175(23.812,2.35) 176(23.812,-2.35) 177(24.447,2.35) 178(24.447,-2.35) 179(25.082,2.35) 180(25.082,-2.35) 181(25.717,2.35) 182(25.717,-2.35) 183(26.352,2.35) 184(26.352,-2.35) 185(26.987,2.35) 186(26.987,-2.35) 187(27.622,2.35) 188(27.622,-2.35) 189(28.258,2.35) 190(28.258,-2.35) 191(28.892,2.35) 192(28.892,-2.35) 193(29.527,2.35) 194(29.527,-2.35) 195(30.162,2.35) 196(30.162,-2.35) 197(30.797,2.35) 198(30.797,-2.35) 199(31.432,2.35) 200(31.432,-2.35)
  round 0.7 hole 0.7: 1(32.685,0)
  rect 2.5x2 smd: M1(-34.5,0) M2(34.5,0)
Top Overlay:
  lines w0.203: -35.6,-1.9 -35.6,-1.5 ; -35,-1.5 -35.6,-1.5 ; -35,1.5 -35.6,1.5 -35.6,1.875 -34.375,3.1 -33.6,3.1 -33.6,2.4 ; -34.4,-3.1 -33.6,-3.1 ; -33.6,-2.4 -33.6,-3.1 ; -32,-2 -33.75,-2 -33.75,0 -33,0 -33,2 -32,2 ; -32,-1 cw(c-32,-0.75) -32.25,-0.75 -32.25,0.75 cw(c-32,0.75) -32,1 ; 32,-2 33.75,-2 33.75,0 33,0 33,2 32,2 ; 32,-1 ccw(c32,-0.75) 32.25,-0.75 32.25,0.75 ccw(c32,0.75) 32,1 ; 33.6,-2.4 33.6,-3.1 35.6,-3.1 35.6,-1.5 35,-1.5 ; 33.6,2.4 33.6,3.1 35.6,3.1 35.6,1.5 35,1.5 ; -35.6,-1.5 -35.6,-3.1 -33.6,-3.1
Top Solder:
  drawing of 200 lines, arcs and shapes, not listed
Mechanical 16:
  drawing of 208 lines, arcs and shapes, not listed

## 70543-02 [mil]
pads (2):
  oval 60x120 hole 40: 1(-50,0) 2(50,0)
Top Overlay:
  lines w10: -150,-112.5 -150,112.5 150,112.5 150,-112.5 137.5,-112.5 137.5,-150 -137.5,-150 -137.5,-112.5 -150,-112.5
Mechanical 16:
  rectangle: 40.63,-9.37 59.37,9.37
  rectangle: -59.37,-9.37 -40.63,9.37
  lines w2: -112.5,-87.5 -125,-87.5 -125,87.5 125,87.5 125,-87.5 112.5,-87.5 ; -112.5,-87.5 112.5,-87.5 ; -112.5,-87.5 -112.5,-125 112.5,-125 112.5,-87.5
  text "1" at -112.5,-62.5 h62

## 70543-03 [mil]
pads (3):
  oval 60x120 hole 40: 1(-100,0) 2(0,0) 3(100,0)
Top Overlay:
  lines w10: -200,-112.5 -200,112.5 200,112.5 200,-112.5 137.5,-112.5 137.5,-150 -137.5,-150 -137.5,-112.5 -200,-112.5
Mechanical 16:
  rectangle: -9.37,-9.37 9.37,9.37
  rectangle: -109.37,-9.37 -90.63,9.37
  rectangle: 90.63,-9.37 109.37,9.37
  lines w2: -112.5,-87.5 -175,-87.5 -175,87.5 175,87.5 175,-87.5 112.5,-87.5 ; -112.5,-87.5 112.5,-87.5 ; -112.5,-87.5 -112.5,-125 112.5,-125 112.5,-87.5
  text "1" at -162.5,-62.5 h62

## 70543-04 [mil]
pads (4):
  oval 60x120 hole 40: 1(-150,0) 2(-50,0) 3(50,0) 4(150,0)
Top Overlay:
  lines w10: -250,-112.5 -250,112.5 250,112.5 250,-112.5 137.5,-112.5 137.5,-150 -137.5,-150 -137.5,-112.5 -250,-112.5
Mechanical 16:
  rectangle: -59.37,-9.37 -40.63,9.37
  rectangle: -159.37,-9.37 -140.63,9.37
  rectangle: 140.63,-9.37 159.37,9.37
  rectangle: 40.63,-9.37 59.37,9.37
  lines w2: -112.5,-87.5 -225,-87.5 -225,87.5 225,87.5 225,-87.5 112.5,-87.5 ; -112.5,-87.5 112.5,-87.5 ; -112.5,-87.5 -112.5,-125 112.5,-125 112.5,-87.5
  text "1" at -212.5,-62.5 h62

## 70543-05 [mil]
pads (5):
  oval 60x120 hole 40: 1(-200,0) 2(-100,0) 3(0,0) 4(100,0) 5(200,0)
Top Overlay:
  lines w10: -300,-112.5 -300,112.5 300,112.5 300,-112.5 137.5,-112.5 137.5,-150 -137.5,-150 -137.5,-112.5 -300,-112.5
Mechanical 16:
  rectangle: -109.37,-9.37 -90.63,9.37
  rectangle: -209.37,-9.37 -190.63,9.37
  rectangle: 90.63,-9.37 109.37,9.37
  rectangle: -9.37,-9.37 9.37,9.37
  rectangle: 190.63,-9.37 209.37,9.37
  lines w2: -112.5,-87.5 -275,-87.5 -275,87.5 275,87.5 275,-87.5 112.5,-87.5 ; -112.5,-87.5 112.5,-87.5 ; -112.5,-87.5 -112.5,-125 112.5,-125 112.5,-87.5
  text "1" at -262.5,-62.5 h62

## 70543-06 [mil]
pads (6):
  oval 60x120 hole 40: 1(-250,0) 2(-150,0) 3(-50,0) 4(50,0) 5(150,0) 6(250,0)
Top Overlay:
  lines w10: -350,-112.5 -350,112.5 350,112.5 350,-112.5 137.5,-112.5 137.5,-150 -137.5,-150 -137.5,-112.5 -350,-112.5
Mechanical 16:
  rectangle: -159.37,-9.37 -140.63,9.37
  rectangle: -259.37,-9.37 -240.63,9.37
  rectangle: 40.63,-9.37 59.37,9.37
  rectangle: -59.37,-9.37 -40.63,9.37
  rectangle: 240.63,-9.37 259.37,9.37
  rectangle: 140.63,-9.37 159.37,9.37
  lines w2: -112.5,-87.5 -325,-87.5 -325,87.5 325,87.5 325,-87.5 112.5,-87.5 ; -112.5,-87.5 112.5,-87.5 ; -112.5,-87.5 -112.5,-125 112.5,-125 112.5,-87.5
  text "1" at -312.5,-62.5 h62

## 70543-07 [mil]
pads (7):
  oval 60x120 hole 40: 1(-300,0) 2(-200,0) 3(-100,0) 4(0,0) 5(100,0) 6(200,0) 7(300,0)
Top Overlay:
  lines w10: -400,-112.5 -400,112.5 400,112.5 400,-112.5 137.5,-112.5 137.5,-150 -137.5,-150 -137.5,-112.5 -400,-112.5
Mechanical 16:
  rectangle: -209.37,-9.37 -190.63,9.37
  rectangle: -309.37,-9.37 -290.63,9.37
  rectangle: -9.37,-9.37 9.37,9.37
  rectangle: -109.37,-9.37 -90.63,9.37
  rectangle: 190.63,-9.37 209.37,9.37
  rectangle: 90.63,-9.37 109.37,9.37
  rectangle: 290.63,-9.37 309.37,9.37
  lines w2: -112.5,-87.5 -375,-87.5 -375,87.5 375,87.5 375,-87.5 112.5,-87.5 ; -112.5,-87.5 112.5,-87.5 ; -112.5,-87.5 -112.5,-125 112.5,-125 112.5,-87.5
  text "1" at -362.5,-62.5 h62

## 70543-08 [mil]
pads (8):
  oval 60x120 hole 40: 1(-350,0) 2(-250,0) 3(-150,0) 4(-50,0) 5(50,0) 6(150,0) 7(250,0) 8(350,0)
Top Overlay:
  lines w10: -450,-112.5 -450,112.5 450,112.5 450,-112.5 137.5,-112.5 137.5,-150 -137.5,-150 -137.5,-112.5 -450,-112.5
Mechanical 16:
  rectangle: -259.37,-9.37 -240.63,9.37
  rectangle: -359.37,-9.37 -340.63,9.37
  rectangle: -59.37,-9.37 -40.63,9.37
  rectangle: -159.37,-9.37 -140.63,9.37
  rectangle: 140.63,-9.37 159.37,9.37
  rectangle: 40.63,-9.37 59.37,9.37
  rectangle: 340.63,-9.37 359.37,9.37
  rectangle: 240.63,-9.37 259.37,9.37
  lines w2: -112.5,-87.5 -425,-87.5 -425,87.5 425,87.5 425,-87.5 112.5,-87.5 ; -112.5,-87.5 112.5,-87.5 ; -112.5,-87.5 -112.5,-125 112.5,-125 112.5,-87.5
  text "1" at -412.5,-62.5 h62

## 70543-09 [mil]
pads (9):
  oval 60x120 hole 40: 1(-400,0) 2(-300,0) 3(-200,0) 4(-100,0) 5(0,0) 6(100,0) 7(200,0) 8(300,0) 9(400,0)
Top Overlay:
  lines w10: -500,-112.5 -500,112.5 500,112.5 500,-112.5 137.5,-112.5 137.5,-150 -137.5,-150 -137.5,-112.5 -500,-112.5
Mechanical 16:
  rectangle: -309.37,-9.37 -290.63,9.37
  rectangle: -409.37,-9.37 -390.63,9.37
  rectangle: -109.37,-9.37 -90.63,9.37
  rectangle: -209.37,-9.37 -190.63,9.37
  rectangle: 90.63,-9.37 109.37,9.37
  rectangle: -9.37,-9.37 9.37,9.37
  rectangle: 290.63,-9.37 309.37,9.37
  rectangle: 190.63,-9.37 209.37,9.37
  rectangle: 390.63,-9.37 409.37,9.37
  lines w2: -112.5,-87.5 -475,-87.5 -475,87.5 475,87.5 475,-87.5 112.5,-87.5 ; -112.5,-87.5 112.5,-87.5 ; -112.5,-87.5 -112.5,-125 112.5,-125 112.5,-87.5
  text "1" at -462.5,-62.5 h62

## 70543-10 [mil]
pads (10):
  oval 60x120 hole 40: 1(-450,0) 2(-350,0) 3(-250,0) 4(-150,0) 5(-50,0) 6(50,0) 7(150,0) 8(250,0) 9(350,0) 10(450,0)
Top Overlay:
  lines w10: -550,-112.5 -550,112.5 550,112.5 550,-112.5 137.5,-112.5 137.5,-150 -137.5,-150 -137.5,-112.5 -550,-112.5
Mechanical 16:
  rectangle: -359.37,-9.37 -340.63,9.37
  rectangle: -459.37,-9.37 -440.63,9.37
  rectangle: -159.37,-9.37 -140.63,9.37
  rectangle: -259.37,-9.37 -240.63,9.37
  rectangle: 40.63,-9.37 59.37,9.37
  rectangle: -59.37,-9.37 -40.63,9.37
  rectangle: 240.63,-9.37 259.37,9.37
  rectangle: 140.63,-9.37 159.37,9.37
  rectangle: 440.63,-9.37 459.37,9.37
  rectangle: 340.63,-9.37 359.37,9.37
  lines w2: -112.5,-87.5 -525,-87.5 -525,87.5 525,87.5 525,-87.5 112.5,-87.5 ; -112.5,-87.5 112.5,-87.5 ; -112.5,-87.5 -112.5,-125 112.5,-125 112.5,-87.5
  text "1" at -512.5,-62.5 h62

## 70543-11 [mil]
pads (11):
  oval 60x120 hole 40: 1(-500,0) 2(-400,0) 3(-300,0) 4(-200,0) 5(-100,0) 6(0,0) 7(100,0) 8(200,0) 9(300,0) 10(400,0) 11(500,0)
Top Overlay:
  lines w10: -600,-112.5 -600,112.5 600,112.5 600,-112.5 137.5,-112.5 137.5,-150 -137.5,-150 -137.5,-112.5 -600,-112.5
Mechanical 16:
  rectangle: -409.37,-9.37 -390.63,9.37
  rectangle: -509.37,-9.37 -490.63,9.37
  rectangle: -209.37,-9.37 -190.63,9.37
  rectangle: -309.37,-9.37 -290.63,9.37
  rectangle: -9.37,-9.37 9.37,9.37
  rectangle: -109.37,-9.37 -90.63,9.37
  rectangle: 190.63,-9.37 209.37,9.37
  rectangle: 90.63,-9.37 109.37,9.37
  rectangle: 390.63,-9.37 409.37,9.37
  rectangle: 290.63,-9.37 309.37,9.37
  rectangle: 490.63,-9.37 509.37,9.37
  lines w2: -112.5,-87.5 -575,-87.5 -575,87.5 575,87.5 575,-87.5 112.5,-87.5 ; -112.5,-87.5 112.5,-87.5 ; -112.5,-87.5 -112.5,-125 112.5,-125 112.5,-87.5
  text "1" at -562.5,-62.5 h62

## 70543-12 [mil]
pads (12):
  oval 60x120 hole 40: 1(-550,0) 2(-450,0) 3(-350,0) 4(-250,0) 5(-150,0) 6(-50,0) 7(50,0) 8(150,0) 9(250,0) 10(350,0) 11(450,0) 12(550,0)
Top Overlay:
  lines w10: -650,-112.5 -650,112.5 650,112.5 650,-112.5 137.5,-112.5 137.5,-150 -137.5,-150 -137.5,-112.5 -650,-112.5
Mechanical 16:
  rectangle: -459.37,-9.37 -440.63,9.37
  rectangle: -559.37,-9.37 -540.63,9.37
  rectangle: -259.37,-9.37 -240.63,9.37
  rectangle: -359.37,-9.37 -340.63,9.37
  rectangle: -59.37,-9.37 -40.63,9.37
  rectangle: -159.37,-9.37 -140.63,9.37
  rectangle: 140.63,-9.37 159.37,9.37
  rectangle: 40.63,-9.37 59.37,9.37
  rectangle: 340.63,-9.37 359.37,9.37
  rectangle: 240.63,-9.37 259.37,9.37
  rectangle: 540.63,-9.37 559.37,9.37
  rectangle: 440.63,-9.37 459.37,9.37
  lines w2: -112.5,-87.5 -625,-87.5 -625,87.5 625,87.5 625,-87.5 112.5,-87.5 ; -112.5,-87.5 112.5,-87.5 ; -112.5,-87.5 -112.5,-125 112.5,-125 112.5,-87.5
  text "1" at -612.5,-62.5 h62

## 70543-13 [mil]
pads (13):
  oval 60x120 hole 40: 1(-600,0) 2(-500,0) 3(-400,0) 4(-300,0) 5(-200,0) 6(-100,0) 7(0,0) 8(100,0) 9(200,0) 10(300,0) 11(400,0) 12(500,0) 13(600,0)
Top Overlay:
  lines w10: -700,-112.5 -700,112.5 700,112.5 700,-112.5 137.5,-112.5 137.5,-150 -137.5,-150 -137.5,-112.5 -700,-112.5
Mechanical 16:
  rectangle: -509.37,-9.37 -490.63,9.37
  rectangle: -609.37,-9.37 -590.63,9.37
  rectangle: -309.37,-9.37 -290.63,9.37
  rectangle: -409.37,-9.37 -390.63,9.37
  rectangle: -109.37,-9.37 -90.63,9.37
  rectangle: -209.37,-9.37 -190.63,9.37
  rectangle: 90.63,-9.37 109.37,9.37
  rectangle: -9.37,-9.37 9.37,9.37
  rectangle: 290.63,-9.37 309.37,9.37
  rectangle: 190.63,-9.37 209.37,9.37
  rectangle: 490.63,-9.37 509.37,9.37
  rectangle: 390.63,-9.37 409.37,9.37
  rectangle: 590.63,-9.37 609.37,9.37
  lines w2: -112.5,-87.5 -675,-87.5 -675,87.5 675,87.5 675,-87.5 112.5,-87.5 ; -112.5,-87.5 112.5,-87.5 ; -112.5,-87.5 -112.5,-125 112.5,-125 112.5,-87.5
  text "1" at -662.5,-62.5 h62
